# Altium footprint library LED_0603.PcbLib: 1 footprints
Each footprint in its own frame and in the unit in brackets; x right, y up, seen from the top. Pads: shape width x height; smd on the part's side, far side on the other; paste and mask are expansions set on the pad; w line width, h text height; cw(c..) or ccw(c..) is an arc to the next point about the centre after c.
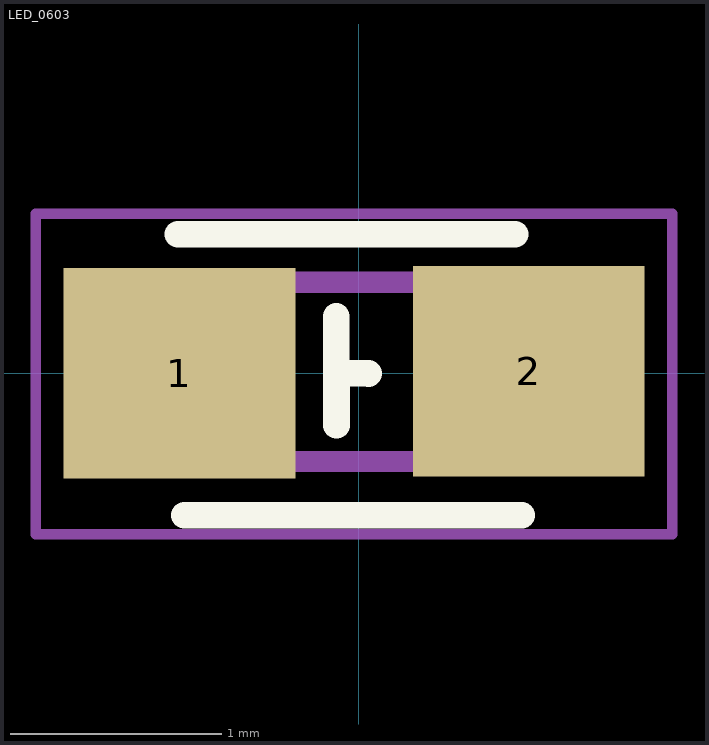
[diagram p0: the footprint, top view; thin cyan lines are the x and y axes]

## LED_0603 [mm]
pads (2):
  rect 1.1x1 smd: 1(-0.85,0) 2(0.808,0.009)
Top Overlay:
  lines w0.127: -0.857,0.66 0.743,0.66 ; -0.826,-0.673 0.774,-0.673 ; -0.106,0.27 -0.105,-0.247 ; -0.102,0.001 0.047,-0.001
Mechanical 13:
  region: -0.338,-0.471 -0.84,-0.471 -0.84,0.48 -0.338,0.48
  region: 0.83,-0.471 0.331,-0.471 0.331,0.48 0.83,0.48
  lines w0.102: -0.356,-0.419 0.356,-0.419 ; -0.356,0.432 0.356,0.432
Mechanical 15:
  lines w0.05: -1.532,-0.764 -1.532,0.756 1.488,0.756 1.488,-0.764 -1.532,-0.764
3D body "LED_0603.STEP": height 0.55, standoff 0, extent -0.925,-0.373 0.676,0.427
